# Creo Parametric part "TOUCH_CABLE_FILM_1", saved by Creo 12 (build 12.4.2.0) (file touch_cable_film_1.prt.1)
Units: Custom; MM, KILOGRAM, SECS

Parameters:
  PTC_WM_ITERATION = "0"
  PTC_WM_VERSION = "-.0"
  PTC_WM_LIFECYCLE_STATE = "In Work"
  PTC_WM_LIFECYCLE = "MO_CADDocument"
  PTC_WM_CREATED_BY = "Maximilian Roepper (Z0017RMS: MO)"
  PTC_WM_CREATED_ON = "18-Sep-26 11:36:42 AM"
  PTC_WM_MODIFIED_BY = "Maximilian Roepper (Z0017RMS: MO)"
  PTC_WM_MODIFIED_ON = "18-Sep-26 11:36:46 AM"
  PDMLINKNUMBER = "PDM000071455152"
  PTC_WM_NAME = "touch_cable_film_1.prt"
  PTC_WM_NUMBER = "PDM000071455152"

Other parameters: WEIGHT, WEIGHT_FACTOR, WEIGHT_ADD, _MASS_TEMP, _DIFF_TEMP, MC_ERRORS, SUPPLIER

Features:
  1. coordinate system
  2. datum plane "PRT_YZ"
  3. datum plane "PRT_XY"
  4. datum plane "PRT_XZ"
  5. coordinate system
  6. datum axis
  7. datum axis
  8. datum axis
  9. coordinate system
  10. imported feature
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
Other named items: PRT, SIEMENS_MO, DRW_VIEW_ORG, PRT_X, PRT_Y, PRT_Z, CS0, ROUGH_GROB

Layers: 00_STD_CSYS-KSYS, 01_STD_PLANES-EBENEN, 02_STD_AXES-ACHSEN, 03_STD_CSYS-KSYS, 24_IMPORT_FEAT-IMPORT_KE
